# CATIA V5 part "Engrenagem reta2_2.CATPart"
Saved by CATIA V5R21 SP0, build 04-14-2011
Part number: Engrenagem reta2_2
Definition: Engrenagem reta2_2
Nomenclature: Engrenagem reta25
Source: Unknown
Bounding box of the stored display mesh (mm): x -2.788 to 2.788, y -2.787 to 2.787, z 0 to 0.5
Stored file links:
  C:\Users\beatr\OneDrive\Documents\UNB\2026_1\Pi1\Componentes eletronicos\Engrenagem reta2_2.CATPart
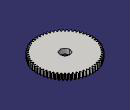
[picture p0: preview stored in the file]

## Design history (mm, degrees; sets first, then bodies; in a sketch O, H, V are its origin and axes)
Body1 "Solid1" (main body)
  Solid1: solid without history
